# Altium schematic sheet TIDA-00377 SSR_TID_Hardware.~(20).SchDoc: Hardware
size 431 x 279 mm; VersionControl_RevNumber: Use project parameter SCH_Rev; Date: Not shown in title block; ApprovedBy: Not shown in title block; CheckedBy: Not shown in title block; Author: Not shown in title block; CompanyName: Not shown in title block; DrawnBy: Tattiana Davenport; Engineer: Not shown in title block; Organization: Not shown in title block; Address1: Not shown in title block; Address2: Not shown in title block; Address3: Not shown in title block; Address4: Not shown in title block; DocumentNumber: 1; Revision: Use project parameter SCH_Rev; SheetNumber: 3; SheetTotal: 3; PageSetup: Record=PageOptions¦CenterHorizontal=True¦CenterVertical=True¦PrintScale=1.00¦XCorrection=1.00¦YCorrection=1.00¦PrintKind=0¦BorderSize=5000000¦LeftOffset=0¦BottomOffset=0¦Orientation=2¦PaperLength=1000¦PaperWidth=1000¦Scale=100¦PaperSource=15¦PrintQuality=600¦MediaType=1¦DitherType=10¦PaperKind=Letter¦PrintScaleMode=1
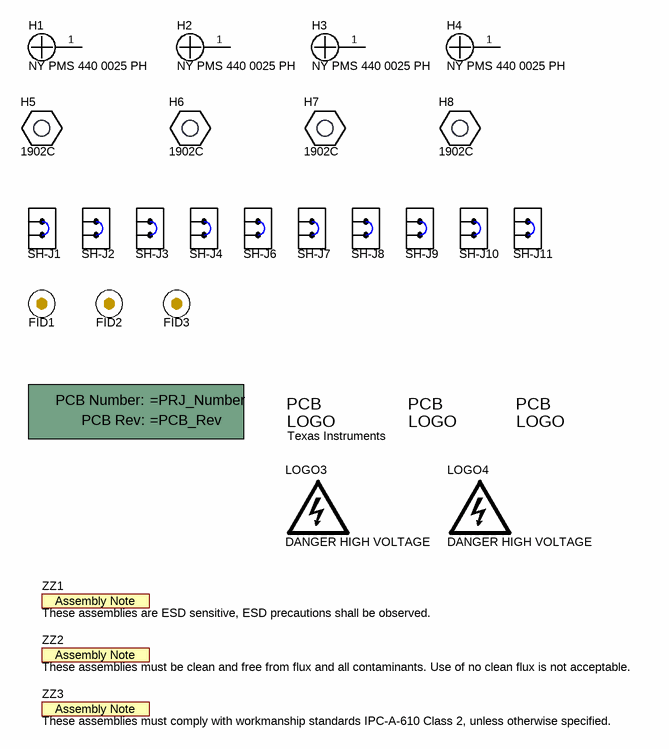
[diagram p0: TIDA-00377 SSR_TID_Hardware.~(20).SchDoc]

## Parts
!PCB1  Printed Circuit Board  (value not drawn)  (mechanical)
FCC_Disclaimer  FCC disclaimer  [FCC_disclaimer]  (value not drawn)  (no BOM)
FID1  Fiducial  [Fiducial10-20]  (value not drawn)
FID2  Fiducial  [Fiducial10-20]  (value not drawn)
FID3  Fiducial  [Fiducial10-20]  (value not drawn)
H1  NY PMS 440 0025 PH  [NY PMS 440 0025 PH]
H2  NY PMS 440 0025 PH  [NY PMS 440 0025 PH]
H3  NY PMS 440 0025 PH  [NY PMS 440 0025 PH]
H4  NY PMS 440 0025 PH  [NY PMS 440 0025 PH]
H5  1902C  [Keystone_1902C]
H6  1902C  [Keystone_1902C]
H7  1902C  [Keystone_1902C]
H8  1902C  [Keystone_1902C]
Logo1  Texas Instruments  [TI_Stacked_Overlay_Small]  (no BOM)
LOGO3  DANGER HIGH VOLTAGE  [IEC_HighVoltage_Small]  (no BOM)
LOGO4  DANGER HIGH VOLTAGE  [IEC_HighVoltage_Small]  (no BOM)
Logo?  EU RoHS Exempt Logo  [EURoHS_Exempt_60mil]  (value not drawn)  (no BOM)
SH-J1  SPC02SYAN  [SPC02SYAN]  (value not drawn)
SH-J2  SPC02SYAN  [SPC02SYAN]  (value not drawn)
SH-J3  SPC02SYAN  [SPC02SYAN]  (value not drawn)
SH-J4  SPC02SYAN  [SPC02SYAN]  (value not drawn)
SH-J6  SPC02SYAN  [SPC02SYAN]  (value not drawn)
SH-J7  SPC02SYAN  [SPC02SYAN]  (value not drawn)
SH-J8  SPC02SYAN  [SPC02SYAN]  (value not drawn)
SH-J9  SPC02SYAN  [SPC02SYAN]  (value not drawn)
SH-J10  SPC02SYAN  [SPC02SYAN]  (value not drawn)
SH-J11  SPC02SYAN  [SPC02SYAN]  (value not drawn)
ZZ1  These assemblies are ESD sensitive, ESD precautions shall be observed.  [AssemblyNote]  (no BOM)
ZZ2  These assemblies must be clean and free from flux and all contaminants. Use of no clean flux is not acceptable.  [AssemblyNote]  (no BOM)
ZZ3  These assemblies must comply with workmanship standards IPC-A-610 Class 2, unless otherwise specified.  [AssemblyNote]  (no BOM)

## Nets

Not connected (* = marked no-connect by the designer): H1 1; H2 1; H3 1; H4 1

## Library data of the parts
!PCB1 = PCB: Manufacturer: Any; SymbolCreator: a0412235
FCC_Disclaimer = FCC_disclaimer: SymbolCreator: a0412235
FID1-FID3 = Fiducial: Fiducial mark.  There is nothing to buy or mount.; SymbolCreator: codlsc
H1-H4 = NY PMS 440 0025 PH: Machine Screw, Round, #4-40 x 1/4, Nylon, Philips panhead; Manufacturer: B&F Fastener Supply; CompType: Hardware; SymbolCreator: codlsc; U/M: EA
H5-H8 = 1902C: Standoff, Hex, 0.5"L #4-40 Nylon; Manufacturer: Keystone; CompType: Hardware
Logo1 = TI_Logo: Texas Instrument Corporate Signature; SymbolCreator: codlsc
LOGO3 LOGO4 = IEC_HighVoltage: IEC 61010-1 High Voltage Warning; SymbolCreator: a0412235
Logo? = EURoHS_Exempt: SymbolCreator: a0412235
SH-J1-SH-J4 SH-J6-SH-J11 = SPC02SYAN: Shunt, 100mil, Flash Gold, Black; Manufacturer: Sullins Connector Solutions; Value: 1x2; Note: You can "mate" this to a header by matching the designator.  i.e. use SH-J3 for header J3
ZZ1-ZZ3 = AssemblyNote: SymbolCreator: codlsc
